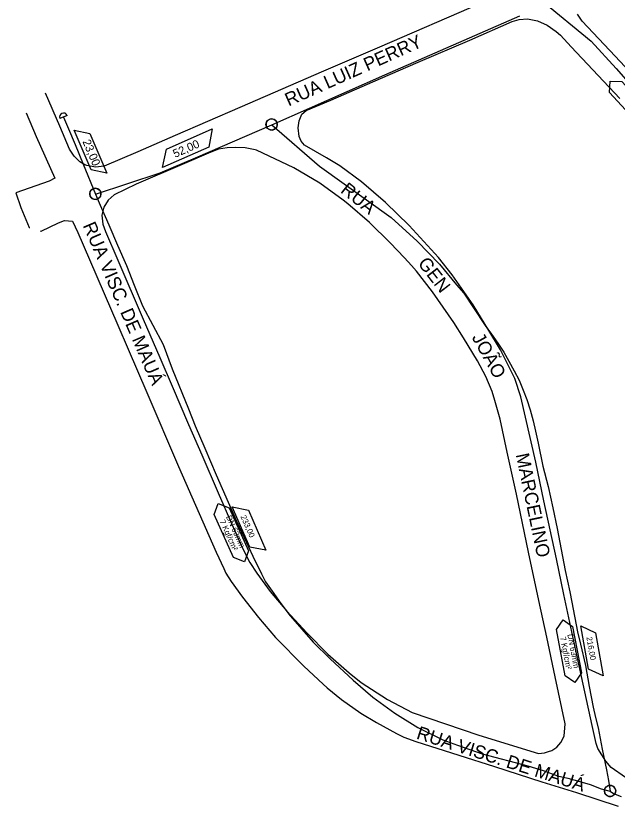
# Model space of a CAD drawing. Extents: x 656692 to 673945, y 7585994 to 7599066.
# Drawn here: x 668330.1 to 668654.9, y 7594704.8 to 7595131.3 of the extents above; entities that cross this region are included whole.
import ezdxf

# ---------------------------------------------------------------- set-up
doc = ezdxf.new("R2010")
doc.units = 0
for name, color, linetype in [('LOGRADOURO', 7, 'Continuous'), ('LOGRADOURO_TEXTO', 7, 'Continuous'), ('SIMBOLO', 7, 'Continuous'), ('TEXTO', 7, 'Continuous'), ('TUBO_PEAD_GN_63', 7, 'Continuous')]:
    doc.layers.add(name, color=color, linetype=linetype)

# ---------------------------------------------------------------- blocks, each defined once
blk = doc.blocks.new('INTERLIGACAO_9')
at = {"layer": 'SIMBOLO'}
blk.add_circle((0, 0), 4.19, dxfattribs=at)
for start, end in [(0, 180), (180, 0)]:
    blk.add_arc((0, 0), 4.19, start, end, dxfattribs=at)

msp = doc.modelspace()

# ---------------------------------------------------------------- linework, layer by layer
at = {"layer": 'LOGRADOURO'}
for points in [[(668586.17, 7595142.17), (668584.61, 7595140.11), (668581.34, 7595138.22), (668526.44, 7595114.47), (668496.18, 7595101.48), (668451.14, 7595081.88), (668416.13, 7595066.8), (668395.98, 7595058.02), (668377.86, 7595050.28), (668373.21, 7595049.71), (668368.41, 7595050.52), (668367.4, 7595050.88), (668364.76, 7595052.52), (668361.54, 7595055.64), (668359.18, 7595059.46), (668353.9, 7595071.87), (668346.14, 7595089.62)], [(668659.36, 7594720.25), (668651.53, 7594725.64), (668648.66, 7594729.02), (668644.38, 7594736.01), (668643.54, 7594738.56), (668641.3, 7594748.35), (668637.33, 7594766.52), (668632.5, 7594788.75), (668625.99, 7594819.08), (668621.99, 7594838.36), (668615.26, 7594869.59), (668610.83, 7594890.4), (668605.39, 7594914.75), (668602.76, 7594925.74), (668599.6, 7594935.55), (668591.75, 7594951.04), (668585.59, 7594961.57), (668577.07, 7594975.34), (668565.75, 7594991.54), (668558.29, 7595000.93), (668542.56, 7595018.09), (668529.76, 7595030.51), (668516.7, 7595041.81), (668505.16, 7595050.31), (668497.94, 7595054.63), (668485.93, 7595061.5), (668484.14, 7595063.69), (668483.14, 7595066.26), (668482.49, 7595070.89), (668483.03, 7595074.72), (668484.63, 7595078.28), (668486.88, 7595080.16), (668500.26, 7595085.81), (668526.96, 7595097.42), (668547.46, 7595106.35), (668575.28, 7595118.28), (668598.16, 7595128.29), (668601.87, 7595129.35), (668606.4, 7595129.71), (668611.74, 7595128.71), (668616.96, 7595126.2), (668621.98, 7595122.88), (668624.17, 7595120.9), (668629.94, 7595114.68), (668656.26, 7595086.79)], [(668672.43, 7595089.62), (668653.7, 7595109.51), (668635.95, 7595128.47), (668633.45, 7595132.15)], [(668335.69, 7595079.01), (668341.09, 7595066.25), (668351.1, 7595043.72), (668348.03, 7595042.11), (668330.09, 7595035.73), (668332.77, 7595027.97), (668337.37, 7595017.16), (668337.76, 7595017.04)], [(668343.22, 7595015.33), (668343.71, 7595015.18), (668353.23, 7595019.65), (668356.43, 7595020.9), (668360.8, 7595020.52), (668363.6, 7595014.43), (668366.49, 7595007.68), (668385.18, 7594964.35), (668390.79, 7594951.51), (668400.87, 7594928.09), (668417.92, 7594888.04), (668438.3, 7594841.97), (668442.48, 7594833), (668443.6, 7594830.62), (668446.35, 7594826.09), (668452.5, 7594817.52), (668461.15, 7594806.58), (668470.4, 7594795.89), (668485.66, 7594780.32), (668496.14, 7594770.66), (668498.21, 7594768.65), (668506.04, 7594762.33), (668516.48, 7594755.06), (668524.8, 7594749.96), (668535.66, 7594743.96), (668539.59, 7594742.06), (668546.04, 7594739.79), (668569.25, 7594732.34), (668588.51, 7594726.21), (668614.12, 7594717.89), (668632.94, 7594712.16), (668655.4, 7594704.8)]]:
    msp.add_lwpolyline(points, dxfattribs=at)
msp.add_lwpolyline([(668615.64, 7594733.68), (668617.79, 7594734.23), (668619.61, 7594734.9), (668622.2, 7594736.6), (668624.47, 7594739.12), (668626.27, 7594742.58), (668626.67, 7594749.16), (668621.27, 7594774.53), (668616.85, 7594795.95), (668612.48, 7594815.78), (668606.95, 7594841.93), (668600.54, 7594873.23), (668595.51, 7594895.85), (668591.67, 7594913.67), (668588.75, 7594923.81), (668587.32, 7594928.51), (668583.97, 7594936.69), (668579.49, 7594945.06), (668571.83, 7594957.62), (668566.68, 7594965.85), (668555.05, 7594982.44), (668546.39, 7594993.61), (668543.85, 7594996.51), (668540.02, 7595000.7), (668532.22, 7595008.91), (668521.17, 7595019.73), (668509.4, 7595029.9), (668506.88, 7595031.9), (668494.24, 7595040.96), (668480.2, 7595049.23), (668460.13, 7595058.85), (668459.27, 7595059.09), (668453.87, 7595060.06), (668448.78, 7595060.26), (668444.16, 7595060.08), (668439.55, 7595059.34), (668435.38, 7595057.74), (668419.85, 7595051.17), (668395.1, 7595040.42), (668383.28, 7595034.81), (668379.91, 7595031.8), (668377.67, 7595028.16), (668376.59, 7595023.69), (668377.1, 7595018.85), (668378.49, 7595014.98), (668385.2, 7594999.52), (668398.91, 7594967.57), (668407.8, 7594946.93), (668414.58, 7594931.55), (668423.39, 7594910.87), (668430.57, 7594894.35), (668439.42, 7594873.94), (668446.67, 7594857.09), (668452.41, 7594844.33), (668456.47, 7594836.26), (668460.17, 7594830.64), (668467.48, 7594820.71), (668476.52, 7594810.01), (668487.19, 7594798.37), (668498.62, 7594786.85), (668510.2, 7594776.85), (668516.67, 7594771.52), (668530.85, 7594762.43), (668544.16, 7594755.34), (668580.13, 7594743.22), (668612.32, 7594733.27)], close=True, dxfattribs=at)
at = {"layer": 'SIMBOLO'}
for points in [[(668651.04, 7595096.15), (668657.29, 7595095.9), (668674.6, 7595077.12), (668674.34, 7595070.87), (668668.09, 7595071.13), (668650.78, 7595089.9), (668651.04, 7595096.15)], [(668439.43, 7594868.12), (668445.28, 7594865.89), (668455.75, 7594842.6), (668453.53, 7594836.75), (668447.68, 7594838.97), (668437.21, 7594862.27), (668439.43, 7594868.12)], [(668625.64, 7594805.39), (668630.8, 7594801.86), (668635.53, 7594776.77), (668632, 7594771.6), (668626.84, 7594775.13), (668622.11, 7594800.22), (668625.64, 7594805.39)]]:
    msp.add_lwpolyline(points, dxfattribs=at)
at = {"layer": 'TEXTO'}
for points in [[(668370.16, 7595067.82), (668379.31, 7595046.47), (668370.82, 7595048.15), (668361.61, 7595069.63), (668370.16, 7595067.82)], [(668411.4, 7595059.4), (668436.22, 7595070.34), (668434.37, 7595060.4), (668409.4, 7595049.39), (668411.4, 7595059.4)], [(668455.67, 7594864.54), (668465.09, 7594843), (668456.48, 7594844.63), (668447, 7594866.3), (668455.67, 7594864.54)], [(668455.67, 7594864.53), (668465.09, 7594843), (668456.48, 7594844.63), (668447, 7594866.3), (668455.67, 7594864.53)], [(668643.16, 7594798.31), (668647.29, 7594775.17), (668639.3, 7594778.77), (668635.15, 7594802.05), (668643.16, 7594798.31)], [(668643.16, 7594798.3), (668647.29, 7594775.16), (668639.3, 7594778.76), (668635.15, 7594802.05), (668643.16, 7594798.3)]]:
    msp.add_lwpolyline(points, dxfattribs=at)
at = {"layer": 'TUBO_PEAD_GN_63'}
msp.add_line((668357.85, 7595077.55), (668353.9, 7595075.9), dxfattribs=at)
for points in [[(668613.55, 7595140.09), (668640.82, 7595117.7), (668654.36, 7595102.86), (668669.76, 7595085.23)], [(668373.12, 7595035.14), (668408.12, 7595046.68), (668427.06, 7595054.62), (668468.32, 7595072.58), (668529.33, 7595099.51), (668602.2, 7595131.34)], [(668355.87, 7595076.73), (668358.58, 7595070.4), (668362.22, 7595061.92), (668366.54, 7595051.3), (668373.12, 7595035.14), (668375.67, 7595029.08), (668380.33, 7595018.56), (668385.03, 7595007.5), (668389.91, 7594996.65), (668394.08, 7594985.92), (668398.54, 7594974.8), (668409.75, 7594953.87), (668414.5, 7594940.87), (668423.43, 7594919.32), (668427.03, 7594910.05), (668432.26, 7594898.09), (668438.36, 7594883.59), (668444.81, 7594868.86), (668449.36, 7594858.71), (668453.5, 7594849.73), (668458.11, 7594839.81), (668462.86, 7594830.25), (668464.95, 7594825.97), (668469.52, 7594819.64), (668473.28, 7594814.25), (668478.25, 7594807.46), (668484.49, 7594800.3), (668490.73, 7594793.28), (668499.87, 7594784.29), (668512.33, 7594772.78), (668522.86, 7594763.71), (668534.79, 7594755.09), (668547.21, 7594747.25), (668560.69, 7594740.63), (668568.64, 7594737.68), (668581.93, 7594733.1), (668606.67, 7594726.55), (668614.91, 7594723.99), (668622.68, 7594721.15), (668628.23, 7594720), (668634.61, 7594718.1), (668640.2, 7594716.45), (668646.12, 7594714.19), (668651.09, 7594712.92), (668652.78, 7594711.73), (668656.94, 7594710.06)], [(668468.32, 7595072.58), (668494.05, 7595050.23), (668532.81, 7595022.5), (668546.88, 7595009.79), (668558.95, 7594997.32), (668568.14, 7594986.24), (668571.95, 7594981.65), (668577.32, 7594973.77), (668583.64, 7594964.3), (668586.96, 7594959.58), (668590.42, 7594954.73), (668593.61, 7594949.84), (668596.35, 7594944.91), (668599.19, 7594939.76), (668601.85, 7594934.65), (668604.04, 7594929.4), (668606.1, 7594924.28), (668607.86, 7594918.73), (668609.44, 7594912.84), (668610.71, 7594907.24), (668612.2, 7594900.63), (668614.72, 7594888.38), (668617.55, 7594877.27), (668620.09, 7594865.83), (668622.39, 7594854.67), (668624.54, 7594843.27), (668626.84, 7594831.91), (668629.26, 7594820.54), (668630.4, 7594814.94), (668633.41, 7594798.95), (668635.1, 7594792.21), (668637.67, 7594780.8), (668639.66, 7594769.33), (668641.9, 7594758.31), (668643.21, 7594752.61), (668644.62, 7594747.07), (668646.71, 7594735.54), (668649.02, 7594724.45), (668650.09, 7594718.75), (668651.09, 7594712.92)]]:
    msp.add_lwpolyline(points, dxfattribs=at)
msp.add_arc((668355.87, 7595076.73), 2.14, 22.7573, 202.7573, dxfattribs=at)

# ---------------------------------------------------------------- block references
at = {"layer": 'SIMBOLO', "xscale": 0.7229249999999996, "yscale": 0.7229249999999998, "rotation": 166.312122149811}
for p in [(668468.23, 7595072.69), (668373.03, 7595035.26), (668651, 7594713.03)]:
    msp.add_blockref('INTERLIGACAO_9', p, dxfattribs=at)

# ---------------------------------------------------------------- texts
at = {"layer": 'LOGRADOURO_TEXTO'}
for s, rotation, p in [('RUA LUIZ PERRY', 24.1047, (668477.41, 7595082.35)), ('RUA ', 321.7463, (668504.97, 7595036.35)), ('RUA VISC. DE MAUÁ', 293.3948, (668366.14, 7595018.23)), ('GEN ', 307.734, (668546.89, 7594997.65)), ('JOÃO ', 299.0684, (668576.14, 7594957.78)), ('MARCELINO', 281.8518, (668600.03, 7594894.54)), ('RUA VISC. DE MAUÁ', 342.3342, (668545.97, 7594741.31))]:
    msp.add_text(s, height=7.2, rotation=rotation, dxfattribs=at).set_placement(p)
at = {"layer": 'TEXTO'}
for s, height, rotation, p in [('23,00', 4.447, 293.1976, (668366.01, 7595063.5)), ('52,00', 4.447, 23.7946, (668416.13, 7595054.62)), ('DN 63mm', 3.113, 294.2057, (668443.51, 7594860.93)), ('233,00', 3.113, 293.6348, (668451.38, 7594861.09)), ('7 Kgf/cm²', 3.113, 294.2057, (668440.05, 7594858.58)), ('DN 63mm', 3.113, 280.6723, (668627.92, 7594797.45)), ('7 Kgf/cm²', 3.113, 280.6723, (668624, 7594795.97)), ('216,00', 3.113, 280.1014, (668638.19, 7594795.96))]:
    msp.add_text(s, height=height, rotation=rotation, dxfattribs=at).set_placement(p)

doc.saveas('drawing.dxf')
